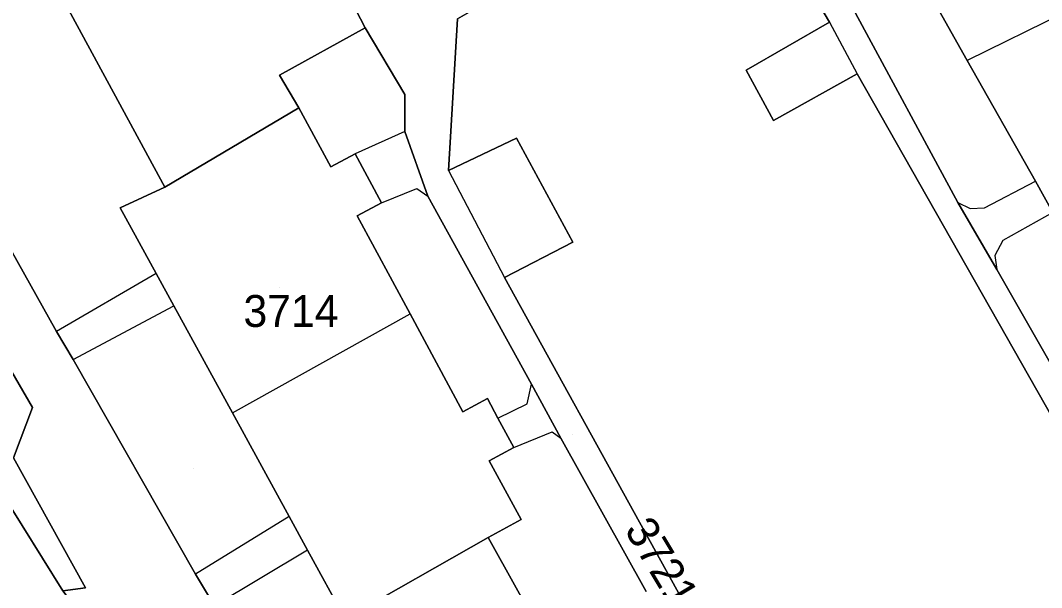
# Model space of a CAD drawing. Extents: x -262715 to -259381, y -1237238 to -1231182.
# Drawn here: x -261814.6 to -261750.6, y -1235487.1 to -1235451.6 of the extents above; entities that cross this region are included whole.
import ezdxf

# ---------------------------------------------------------------- set-up
doc = ezdxf.new("R2010")
doc.units = 0
for name, color, linetype in [('body_kn', 7, 'Continuous'), ('kladpar_druhypozemkov', 7, 'Continuous'), ('kladpar_hranice', 7, 'Continuous'), ('kladpar_parcelnecisla', 7, 'Continuous'), ('kladpar_plochy', 7, 'Continuous'), ('zappar_hrandruhpozemk', 7, 'Continuous')]:
    doc.layers.add(name, color=color, linetype=linetype)

msp = doc.modelspace()

# ---------------------------------------------------------------- linework, layer by layer
at = {"layer": 'body_kn'}
for p, q in [((-261763.9, -1235451.67), (-261763.9, -1235451.67)), ((-261763.9, -1235451.67), (-261763.9, -1235451.67)), ((-261792.99, -1235452.03), (-261792.99, -1235452.03)), ((-261792.99, -1235452.03), (-261792.99, -1235452.03)), ((-261755.28, -1235454.07), (-261755.28, -1235454.07)), ((-261798.35, -1235454.99), (-261798.35, -1235454.99)), ((-261769.12, -1235454.68), (-261769.12, -1235454.68)), ((-261762.17, -1235454.92), (-261762.17, -1235454.92)), ((-261790.51, -1235456.22), (-261790.51, -1235456.22)), ((-261797.13, -1235457.04), (-261797.13, -1235457.04)), ((-261797.13, -1235457.04), (-261797.13, -1235457.04)), ((-261767.41, -1235457.85), (-261767.41, -1235457.85)), ((-261790.49, -1235458.53), (-261790.49, -1235458.53)), ((-261790.49, -1235458.53), (-261790.49, -1235458.53)), ((-261783.5, -1235458.95), (-261783.5, -1235458.95)), ((-261793.61, -1235459.93), (-261793.61, -1235459.93)), ((-261795.14, -1235460.75), (-261795.14, -1235460.75)), ((-261787.77, -1235460.98), (-261787.77, -1235460.98)), ((-261787.77, -1235460.98), (-261787.77, -1235460.98)), ((-261805.54, -1235462.02), (-261805.54, -1235462.02)), ((-261789.75, -1235462.1), (-261789.75, -1235462.1)), ((-261751, -1235461.65), (-261751, -1235461.65)), ((-261789.06, -1235462.59), (-261789.06, -1235462.59)), ((-261808.32, -1235463.31), (-261808.32, -1235463.31)), ((-261791.96, -1235463), (-261791.96, -1235463)), ((-261791.96, -1235463), (-261791.96, -1235463)), ((-261755.87, -1235462.99), (-261755.87, -1235462.99)), ((-261755.87, -1235462.99), (-261755.87, -1235462.99)), ((-261755.1, -1235463.35), (-261755.1, -1235463.35)), ((-261754.19, -1235463.31), (-261754.19, -1235463.31)), ((-261793.48, -1235463.82), (-261793.48, -1235463.82)), ((-261779.97, -1235465.46), (-261779.97, -1235465.46)), ((-261753.04, -1235465.36), (-261753.04, -1235465.36)), ((-261753.55, -1235466.31), (-261753.55, -1235466.31)), ((-261753.42, -1235467.18), (-261753.42, -1235467.18)), ((-261806.07, -1235467.44), (-261806.07, -1235467.44)), ((-261806.07, -1235467.44), (-261806.07, -1235467.44)), ((-261784.25, -1235467.69), (-261784.25, -1235467.69)), ((-261804.96, -1235469.46), (-261804.96, -1235469.46)), ((-261790.17, -1235469.96), (-261790.17, -1235469.96)), ((-261812.32, -1235471.06), (-261812.32, -1235471.06)), ((-261811.28, -1235472.83), (-261811.28, -1235472.83)), ((-261811.28, -1235472.83), (-261811.28, -1235472.83)), ((-261782.57, -1235474.37), (-261782.57, -1235474.37)), ((-261785.33, -1235475.27), (-261785.33, -1235475.27)), ((-261813.82, -1235475.84), (-261813.82, -1235475.84)), ((-261801.29, -1235476.17), (-261801.29, -1235476.17)), ((-261801.29, -1235476.17), (-261801.29, -1235476.17)), ((-261786.86, -1235476.1), (-261786.86, -1235476.1)), ((-261782.83, -1235475.61), (-261782.83, -1235475.61)), ((-261784.67, -1235476.49), (-261784.67, -1235476.49)), ((-261784.67, -1235476.49), (-261784.67, -1235476.49)), ((-261781.27, -1235477.35), (-261781.27, -1235477.35)), ((-261780.72, -1235477.75), (-261780.72, -1235477.75)), ((-261783.67, -1235478.34), (-261783.67, -1235478.34)), ((-261783.67, -1235478.34), (-261783.67, -1235478.34)), ((-261785.21, -1235479.17), (-261785.21, -1235479.17)), ((-261797.74, -1235482.67), (-261797.74, -1235482.67)), ((-261797.74, -1235482.67), (-261797.74, -1235482.67)), ((-261783.22, -1235482.86), (-261783.22, -1235482.86)), ((-261785.29, -1235483.98), (-261785.29, -1235483.98)), ((-261785.29, -1235483.98), (-261785.29, -1235483.98)), ((-261796.59, -1235484.78), (-261796.59, -1235484.78)), ((-261796.59, -1235484.78), (-261796.59, -1235484.78)), ((-261803.61, -1235486.27), (-261803.61, -1235486.27))]:
    msp.add_line(p, q, dxfattribs=at)
at = {"layer": 'kladpar_druhypozemkov'}
for p, q in [((-261798.34, -1235468.29), (-261798.34, -1235468.29)), ((-261779.98, -1235477.51), (-261779.98, -1235477.51)), ((-261803.74, -1235479.64), (-261803.74, -1235479.64))]:
    msp.add_line(p, q, dxfattribs=at)
at = {"layer": 'kladpar_hranice'}
for points in [[(-261775.39, -1235487.37), (-261780.72, -1235477.75), (-261782.57, -1235474.37), (-261789.06, -1235462.59), (-261790.49, -1235458.53), (-261790.51, -1235456.22), (-261792.99, -1235452.03), (-261793.87, -1235450.34), (-261790.31, -1235448.32), (-261789.57, -1235449.38), (-261787.25, -1235445.39), (-261787.35, -1235444), (-261787.76, -1235442.73), (-261785.22, -1235440.2), (-261773.5, -1235433.51), (-261771.33, -1235432.27), (-261753.4, -1235422.04)], [(-261753.4, -1235422.04), (-261752.11, -1235424.22), (-261773.09, -1235436.12), (-261774.22, -1235436.76), (-261783.26, -1235442.31), (-261786.03, -1235450.8), (-261787.21, -1235451.46), (-261787.77, -1235460.98), (-261783.5, -1235458.95), (-261779.97, -1235465.46), (-261784.25, -1235467.69), (-261766.01, -1235500.78)], [(-261703.82, -1235554.81), (-261717.49, -1235533.49), (-261720.95, -1235535.54), (-261724.65, -1235529.36), (-261721.21, -1235527.35), (-261741.69, -1235490.92), (-261746.46, -1235482.59), (-261762.17, -1235454.92), (-261767.41, -1235457.85), (-261769.12, -1235454.68), (-261763.9, -1235451.67), (-261773.09, -1235436.12), (-261752.11, -1235424.22), (-261749.95, -1235426.33)], [(-261808.91, -1235424.68), (-261807.73, -1235425.15), (-261806.88, -1235426.13), (-261804.32, -1235431.02), (-261799.43, -1235439.92), (-261802.77, -1235441.9), (-261802.22, -1235442.86), (-261804.18, -1235443.92), (-261805.61, -1235441.27), (-261814.23, -1235445.92), (-261805.54, -1235462.02), (-261808.32, -1235463.31), (-261806.07, -1235467.44), (-261804.96, -1235469.46), (-261801.29, -1235476.17), (-261797.74, -1235482.67), (-261796.59, -1235484.78), (-261794.24, -1235489.08)], [(-261702.44, -1235554.03), (-261718.94, -1235528.05), (-261721.43, -1235523.65), (-261727.61, -1235512.61), (-261729.76, -1235508.8), (-261736.11, -1235497.5), (-261738.53, -1235493.35), (-261744.87, -1235482.21), (-261747.16, -1235478.14), (-261753.42, -1235467.18), (-261755.87, -1235462.99), (-261762.27, -1235451.12), (-261763.94, -1235448.17), (-261769.25, -1235438.72), (-261769.14, -1235437.7), (-261768.42, -1235436.65), (-261749.95, -1235426.33)], [(-261749.95, -1235426.33), (-261768.42, -1235436.65), (-261769.14, -1235437.7), (-261769.25, -1235438.72), (-261763.94, -1235448.17), (-261762.27, -1235451.12), (-261755.87, -1235462.99), (-261753.42, -1235467.18), (-261747.16, -1235478.14), (-261744.87, -1235482.21), (-261738.53, -1235493.35), (-261736.11, -1235497.5), (-261729.76, -1235508.8), (-261727.61, -1235512.61), (-261721.43, -1235523.65), (-261718.94, -1235528.05), (-261702.44, -1235554.03)], [(-261749.91, -1235463.6), (-261751, -1235461.65), (-261755.28, -1235454.07), (-261758.46, -1235448.42), (-261759.63, -1235446.36), (-261764.02, -1235438.55), (-261752.97, -1235432.56)], [(-261749.25, -1235439.25), (-261752.97, -1235432.56), (-261764.02, -1235438.55), (-261759.63, -1235446.36), (-261758.46, -1235448.42), (-261755.28, -1235454.07), (-261751, -1235461.65), (-261749.91, -1235463.6)], [(-261738.88, -1235547.2), (-261741.3, -1235543.14), (-261746.14, -1235534.82), (-261766.01, -1235500.78), (-261784.25, -1235467.69), (-261779.97, -1235465.46), (-261783.5, -1235458.95), (-261787.77, -1235460.98), (-261787.21, -1235451.46), (-261786.03, -1235450.8), (-261783.26, -1235442.31), (-261774.22, -1235436.76), (-261773.09, -1235436.12)], [(-261773.09, -1235436.12), (-261763.9, -1235451.67), (-261769.12, -1235454.68), (-261767.41, -1235457.85), (-261762.17, -1235454.92), (-261746.46, -1235482.59), (-261741.69, -1235490.92), (-261721.21, -1235527.35), (-261724.65, -1235529.36), (-261720.95, -1235535.54), (-261717.49, -1235533.49), (-261703.82, -1235554.81)], [(-261795.74, -1235437.93), (-261794.54, -1235440), (-261790.31, -1235448.32), (-261793.87, -1235450.34), (-261792.99, -1235452.03), (-261798.35, -1235454.99), (-261797.13, -1235457.04), (-261805.54, -1235462.02), (-261814.23, -1235445.92), (-261805.61, -1235441.27), (-261804.18, -1235443.92), (-261802.22, -1235442.86), (-261802.77, -1235441.9), (-261799.43, -1235439.92), (-261795.74, -1235437.93)], [(-261781.78, -1235490.28), (-261785.29, -1235483.98), (-261783.22, -1235482.86), (-261785.21, -1235479.17), (-261783.67, -1235478.34), (-261784.67, -1235476.49), (-261785.33, -1235475.27), (-261786.86, -1235476.1), (-261790.17, -1235469.96), (-261793.48, -1235463.82), (-261791.96, -1235463), (-261793.61, -1235459.93), (-261795.14, -1235460.75), (-261797.13, -1235457.04), (-261798.35, -1235454.99), (-261792.99, -1235452.03)], [(-261792.99, -1235452.03), (-261790.51, -1235456.22), (-261790.49, -1235458.53), (-261789.06, -1235462.59), (-261782.57, -1235474.37), (-261780.72, -1235477.75), (-261775.39, -1235487.37)], [(-261802.42, -1235488.27), (-261803.61, -1235486.27), (-261811.28, -1235472.83), (-261812.32, -1235471.06), (-261821.96, -1235453.82)], [(-261821.96, -1235453.82), (-261812.32, -1235471.06), (-261811.28, -1235472.83), (-261803.61, -1235486.27), (-261802.42, -1235488.27), (-261795.95, -1235500.33), (-261794.73, -1235502.49), (-261787.68, -1235515.55), (-261786.62, -1235517.66), (-261779.53, -1235530.77), (-261778.46, -1235532.52), (-261775.04, -1235538.78), (-261771.8, -1235537.18), (-261769.83, -1235540.88), (-261771.43, -1235541.78), (-261768.63, -1235547.14)], [(-261797.13, -1235457.04), (-261795.14, -1235460.75), (-261793.61, -1235459.93), (-261791.96, -1235463), (-261793.48, -1235463.82), (-261790.17, -1235469.96), (-261786.86, -1235476.1), (-261785.33, -1235475.27), (-261784.67, -1235476.49), (-261783.67, -1235478.34), (-261785.21, -1235479.17), (-261783.22, -1235482.86), (-261785.29, -1235483.98), (-261794.24, -1235489.08), (-261796.59, -1235484.78), (-261797.74, -1235482.67), (-261801.29, -1235476.17), (-261804.96, -1235469.46), (-261806.07, -1235467.44), (-261808.32, -1235463.31), (-261805.54, -1235462.02), (-261797.13, -1235457.04)], [(-261825.65, -1235460.28), (-261824.46, -1235459.56), (-261823.25, -1235459.58), (-261813.82, -1235475.84), (-261815, -1235478.99), (-261810.51, -1235487.13), (-261811.93, -1235487.32), (-261817.04, -1235479.13), (-261819.47, -1235476.24), (-261822.92, -1235473.98), (-261829.68, -1235470.14), (-261825.65, -1235460.28)], [(-261774.39, -1235550.27), (-261778.95, -1235541.86), (-261782.96, -1235536.55), (-261783.1, -1235533.24), (-261784.15, -1235529.72), (-261788.23, -1235531.77), (-261789.46, -1235529.01), (-261787.74, -1235526.24), (-261808.44, -1235488.8), (-261810.24, -1235489.54), (-261811.93, -1235487.32), (-261810.51, -1235487.13), (-261815, -1235478.99), (-261813.82, -1235475.84), (-261823.25, -1235459.58)], [(-261817.04, -1235479.13), (-261811.93, -1235487.32), (-261810.24, -1235489.54), (-261808.44, -1235488.8), (-261787.74, -1235526.24), (-261789.46, -1235529.01), (-261788.23, -1235531.77), (-261787.63, -1235534.99), (-261787.64, -1235538.06), (-261788.08, -1235541.41), (-261790.06, -1235545.16), (-261794.1, -1235552.69), (-261796.04, -1235557.46), (-261794.6, -1235563.43), (-261787.63, -1235575.97), (-261767.43, -1235613.37), (-261766.29, -1235615.83), (-261766.06, -1235620.08)], [(-261794.24, -1235489.08), (-261785.29, -1235483.98)], [(-261785.29, -1235483.98), (-261781.78, -1235490.28)]]:
    msp.add_lwpolyline(points, dxfattribs=at)
at = {"layer": 'kladpar_plochy'}
for points in [[(-261741.69, -1235490.92), (-261746.46, -1235482.59), (-261762.17, -1235454.92), (-261767.41, -1235457.85), (-261769.12, -1235454.68), (-261763.9, -1235451.67), (-261773.09, -1235436.12), (-261752.11, -1235424.22), (-261749.95, -1235426.33), (-261768.42, -1235436.65), (-261769.14, -1235437.7), (-261769.25, -1235438.72), (-261763.94, -1235448.17), (-261762.27, -1235451.12), (-261755.87, -1235462.99), (-261753.42, -1235467.18), (-261747.16, -1235478.14), (-261744.87, -1235482.21), (-261738.53, -1235493.35)], [(-261816.91, -1235436.31), (-261814.39, -1235428.3), (-261813.62, -1235426.98), (-261812.84, -1235426.19), (-261810.3, -1235424.85), (-261808.91, -1235424.68), (-261807.73, -1235425.15), (-261806.88, -1235426.13), (-261804.32, -1235431.02), (-261799.43, -1235439.92), (-261802.77, -1235441.9), (-261802.22, -1235442.86), (-261804.18, -1235443.92), (-261805.61, -1235441.27), (-261814.23, -1235445.92), (-261805.54, -1235462.02), (-261808.32, -1235463.31), (-261806.07, -1235467.44), (-261804.96, -1235469.46), (-261801.29, -1235476.17), (-261797.74, -1235482.67), (-261796.59, -1235484.78), (-261794.24, -1235489.08)], [(-261738.53, -1235493.35), (-261744.87, -1235482.21), (-261747.16, -1235478.14), (-261753.42, -1235467.18), (-261755.87, -1235462.99), (-261762.27, -1235451.12), (-261763.94, -1235448.17), (-261769.25, -1235438.72), (-261769.14, -1235437.7), (-261768.42, -1235436.65), (-261749.95, -1235426.33), (-261748.8, -1235425.86), (-261747.13, -1235425.85), (-261744.14, -1235430.75), (-261742.41, -1235434.07), (-261739.92, -1235438.82), (-261734.23, -1235449.27), (-261731.76, -1235453.87), (-261725.66, -1235465.04), (-261723.31, -1235469.51), (-261717.78, -1235480.54), (-261715.18, -1235485.41), (-261709.63, -1235495.51)], [(-261749.91, -1235463.6), (-261751, -1235461.65), (-261755.28, -1235454.07), (-261758.46, -1235448.42), (-261759.63, -1235446.36), (-261764.02, -1235438.55), (-261752.97, -1235432.56), (-261749.25, -1235439.25)], [(-261749.25, -1235439.25), (-261752.97, -1235432.56), (-261764.02, -1235438.55), (-261759.63, -1235446.36), (-261758.46, -1235448.42), (-261755.28, -1235454.07), (-261751, -1235461.65), (-261749.91, -1235463.6)], [(-261738.88, -1235547.2), (-261741.3, -1235543.14), (-261746.14, -1235534.82), (-261766.01, -1235500.78), (-261784.25, -1235467.69), (-261779.97, -1235465.46), (-261783.5, -1235458.95), (-261787.77, -1235460.98), (-261787.21, -1235451.46), (-261786.03, -1235450.8), (-261783.26, -1235442.31), (-261774.22, -1235436.76), (-261773.09, -1235436.12), (-261763.9, -1235451.67), (-261769.12, -1235454.68), (-261767.41, -1235457.85), (-261762.17, -1235454.92), (-261746.46, -1235482.59), (-261741.69, -1235490.92), (-261721.21, -1235527.35), (-261724.65, -1235529.36), (-261720.95, -1235535.54), (-261717.49, -1235533.49), (-261703.82, -1235554.81)], [(-261775.39, -1235487.37), (-261780.72, -1235477.75), (-261782.57, -1235474.37), (-261789.06, -1235462.59), (-261790.49, -1235458.53), (-261790.51, -1235456.22), (-261792.99, -1235452.03), (-261793.87, -1235450.34)], [(-261787.21, -1235451.46), (-261787.77, -1235460.98), (-261783.5, -1235458.95), (-261779.97, -1235465.46), (-261784.25, -1235467.69), (-261766.01, -1235500.78)], [(-261781.78, -1235490.28), (-261785.29, -1235483.98), (-261783.22, -1235482.86), (-261785.21, -1235479.17), (-261783.67, -1235478.34), (-261784.67, -1235476.49), (-261785.33, -1235475.27), (-261786.86, -1235476.1), (-261790.17, -1235469.96), (-261793.48, -1235463.82), (-261791.96, -1235463), (-261793.61, -1235459.93), (-261795.14, -1235460.75), (-261797.13, -1235457.04), (-261798.35, -1235454.99), (-261792.99, -1235452.03), (-261790.51, -1235456.22), (-261790.49, -1235458.53), (-261789.06, -1235462.59), (-261782.57, -1235474.37), (-261780.72, -1235477.75), (-261775.39, -1235487.37)], [(-261802.42, -1235488.27), (-261803.61, -1235486.27), (-261811.28, -1235472.83), (-261812.32, -1235471.06), (-261821.96, -1235453.82)], [(-261821.96, -1235453.82), (-261812.32, -1235471.06), (-261811.28, -1235472.83), (-261803.61, -1235486.27), (-261802.42, -1235488.27), (-261795.95, -1235500.33), (-261794.73, -1235502.49), (-261787.68, -1235515.55), (-261786.62, -1235517.66), (-261779.53, -1235530.77), (-261778.46, -1235532.52), (-261775.04, -1235538.78), (-261771.8, -1235537.18), (-261769.83, -1235540.88), (-261771.43, -1235541.78), (-261768.63, -1235547.14)], [(-261774.39, -1235550.27), (-261778.95, -1235541.86), (-261782.96, -1235536.55), (-261783.1, -1235533.24), (-261784.15, -1235529.72), (-261788.23, -1235531.77), (-261789.46, -1235529.01), (-261787.74, -1235526.24), (-261808.44, -1235488.8), (-261810.24, -1235489.54), (-261811.93, -1235487.32), (-261810.51, -1235487.13), (-261815, -1235478.99), (-261813.82, -1235475.84), (-261823.25, -1235459.58)], [(-261817.04, -1235479.13), (-261811.93, -1235487.32), (-261810.24, -1235489.54), (-261808.44, -1235488.8), (-261787.74, -1235526.24), (-261789.46, -1235529.01), (-261788.23, -1235531.77), (-261787.63, -1235534.99), (-261787.64, -1235538.06), (-261788.08, -1235541.41), (-261790.06, -1235545.16), (-261794.1, -1235552.69)], [(-261794.24, -1235489.08), (-261785.29, -1235483.98), (-261781.78, -1235490.28)]]:
    msp.add_lwpolyline(points, dxfattribs=at)
for points in [[(-261795.74, -1235437.93), (-261794.54, -1235440), (-261790.31, -1235448.32), (-261793.87, -1235450.34), (-261792.99, -1235452.03), (-261798.35, -1235454.99), (-261797.13, -1235457.04), (-261805.54, -1235462.02), (-261814.23, -1235445.92), (-261805.61, -1235441.27), (-261804.18, -1235443.92), (-261802.22, -1235442.86), (-261802.77, -1235441.9), (-261799.43, -1235439.92)], [(-261797.13, -1235457.04), (-261795.14, -1235460.75), (-261793.61, -1235459.93), (-261791.96, -1235463), (-261793.48, -1235463.82), (-261790.17, -1235469.96), (-261786.86, -1235476.1), (-261785.33, -1235475.27), (-261784.67, -1235476.49), (-261783.67, -1235478.34), (-261785.21, -1235479.17), (-261783.22, -1235482.86), (-261785.29, -1235483.98), (-261794.24, -1235489.08), (-261796.59, -1235484.78), (-261797.74, -1235482.67), (-261801.29, -1235476.17), (-261804.96, -1235469.46), (-261806.07, -1235467.44), (-261808.32, -1235463.31), (-261805.54, -1235462.02)], [(-261825.65, -1235460.28), (-261824.46, -1235459.56), (-261823.25, -1235459.58), (-261813.82, -1235475.84), (-261815, -1235478.99), (-261810.51, -1235487.13), (-261811.93, -1235487.32), (-261817.04, -1235479.13), (-261819.47, -1235476.24), (-261822.92, -1235473.98), (-261829.68, -1235470.14)]]:
    msp.add_lwpolyline(points, close=True, dxfattribs=at)
at = {"layer": 'zappar_hrandruhpozemk'}
for p, q in [((-261744.08, -1235448.55), (-261755.28, -1235454.07)), ((-261763.9, -1235451.67), (-261762.17, -1235454.92)), ((-261790.49, -1235458.53), (-261793.61, -1235459.93)), ((-261787.77, -1235460.98), (-261784.25, -1235467.69)), ((-261791.96, -1235463), (-261789.75, -1235462.1)), ((-261789.75, -1235462.1), (-261789.06, -1235462.59)), ((-261754.19, -1235463.31), (-261751, -1235461.65)), ((-261749.91, -1235463.6), (-261753.04, -1235465.36)), ((-261806.07, -1235467.44), (-261812.32, -1235471.06)), ((-261811.28, -1235472.83), (-261804.96, -1235469.46)), ((-261801.29, -1235476.17), (-261790.17, -1235469.96)), ((-261782.83, -1235475.61), (-261782.57, -1235474.37)), ((-261784.67, -1235476.49), (-261782.83, -1235475.61)), ((-261783.67, -1235478.34), (-261781.27, -1235477.35)), ((-261781.27, -1235477.35), (-261780.72, -1235477.75)), ((-261797.74, -1235482.67), (-261803.61, -1235486.27)), ((-261796.59, -1235484.78), (-261802.42, -1235488.27))]:
    msp.add_line(p, q, dxfattribs=at)
for points in [[(-261755.87, -1235462.99), (-261755.1, -1235463.35), (-261754.19, -1235463.31)], [(-261753.04, -1235465.36), (-261753.55, -1235466.31), (-261753.42, -1235467.18)]]:
    msp.add_lwpolyline(points, dxfattribs=at)

# ---------------------------------------------------------------- texts
at = {"layer": 'kladpar_parcelnecisla'}
msp.add_text('3714', height=2, dxfattribs=at).set_placement((-261800.606, -1235470.78))
msp.add_text('3721', height=2, rotation=301, dxfattribs=at).set_placement((-261776.781, -1235483.499))

doc.saveas('drawing.dxf')
